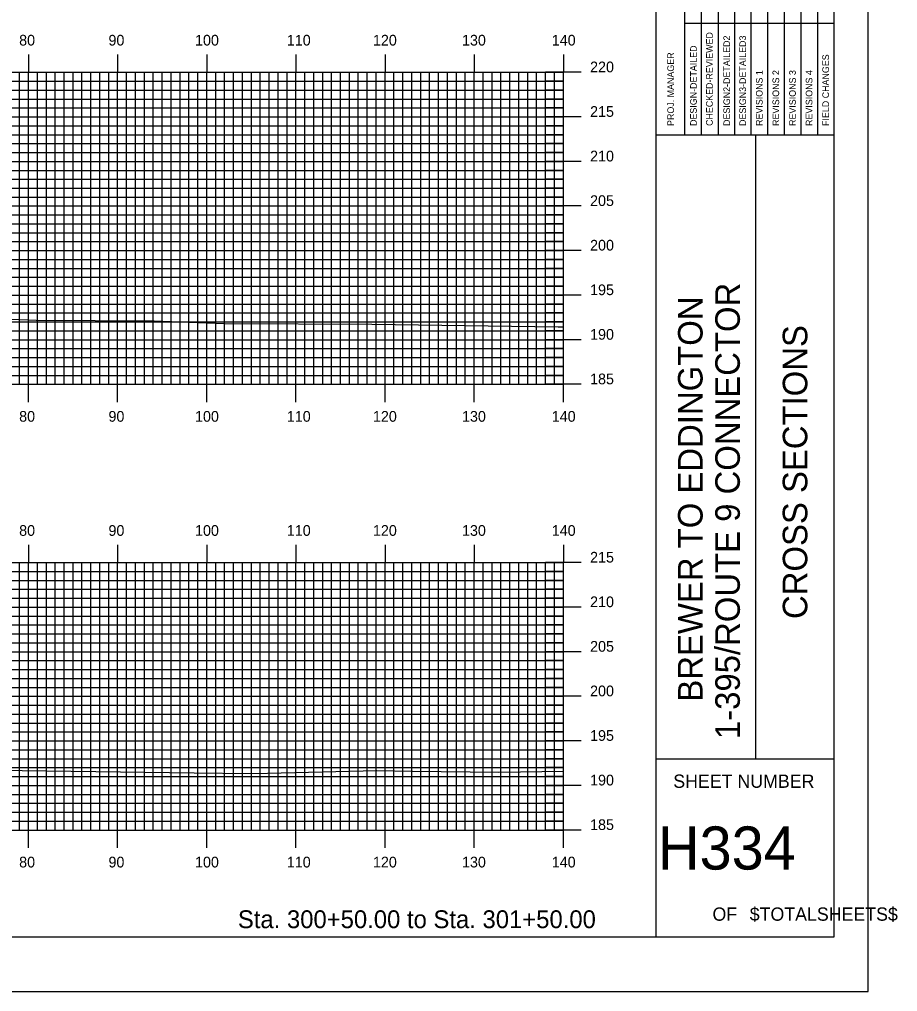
# Model space of a CAD drawing. Extents: x 1815702 to 1816046, y 442591 to 442811.
# Drawn here: x 1815947 to 1816045.5, y 442590.5 to 442699.6 of the extents above; entities that cross this region are included whole.
import ezdxf

# ---------------------------------------------------------------- set-up
doc = ezdxf.new("R2010")
doc.units = 0
for name, color, linetype in [('BORDER', 7, 'Continuous'), ('H_V ANNOTATION', 7, 'Continuous'), ('MAJOR', 7, 'Continuous'), ('MINOR', 7, 'Continuous'), ('PLOT BOUNDARY', 7, 'Continuous'), ('S_Roadway_Centerline', 7, 'Continuous')]:
    doc.layers.add(name, color=color, linetype=linetype)

msp = doc.modelspace()

# ---------------------------------------------------------------- linework, layer by layer
at = {"layer": 'BORDER'}
for p, q in [((1816018.45, 442596.67), (1816018.45, 442806.67)), ((1816018.45, 442686.67), (1816038.45, 442686.67)), ((1816029.63, 442616.67), (1816029.63, 442686.67)), ((1816018.45, 442616.67), (1816038.45, 442616.67))]:
    msp.add_line(p, q, dxfattribs=at)
msp.add_lwpolyline([(1815718.45, 442596.67), (1816038.45, 442596.67), (1816038.45, 442806.67), (1815718.45, 442806.67)], close=True, dxfattribs=at)
for points in [[(1816023.54, 442686.68), (1816023.54, 442721.67)], [(1816025.41, 442721.67), (1816025.41, 442686.68)], [(1816027.27, 442686.68), (1816027.27, 442721.67)], [(1816029.13, 442686.68), (1816029.13, 442721.67)], [(1816031, 442686.68), (1816031, 442721.67)], [(1816032.86, 442686.68), (1816032.86, 442721.67)], [(1816034.72, 442686.68), (1816034.72, 442721.67)], [(1816036.59, 442686.68), (1816036.59, 442721.67)], [(1816021.68, 442686.68), (1816021.68, 442720.26)], [(1816021.68, 442699.17), (1816038.45, 442699.17)]]:
    msp.add_lwpolyline(points, dxfattribs=at)
at = {"layer": 'MAJOR'}
for p, q in [((1815948.05, 442695.67), (1815948.05, 442693.67)), ((1815958.05, 442695.67), (1815958.05, 442693.67)), ((1815968.05, 442695.67), (1815968.05, 442693.67)), ((1815978.05, 442695.67), (1815978.05, 442693.67)), ((1815988.05, 442695.67), (1815988.05, 442693.67)), ((1815998.05, 442695.67), (1815998.05, 442693.67)), ((1816008.05, 442695.67), (1816008.05, 442693.67)), ((1815728.05, 442693.67), (1816008.05, 442693.67)), ((1815728.05, 442693.67), (1816008.05, 442693.67)), ((1815948.05, 442658.67), (1815948.05, 442693.67)), ((1815958.05, 442658.67), (1815958.05, 442693.67)), ((1815968.05, 442658.67), (1815968.05, 442693.67)), ((1815978.05, 442658.67), (1815978.05, 442693.67)), ((1815988.05, 442658.67), (1815988.05, 442693.67)), ((1815998.05, 442658.67), (1815998.05, 442693.67)), ((1816010.05, 442693.67), (1816006.04, 442693.67)), ((1816008.05, 442658.67), (1816008.05, 442693.67)), ((1816008.05, 442658.67), (1816008.05, 442693.67)), ((1815728.05, 442688.67), (1816008.05, 442688.67)), ((1816010.05, 442688.67), (1816006.04, 442688.67)), ((1815728.05, 442683.67), (1816008.05, 442683.67)), ((1816010.05, 442683.67), (1816006.04, 442683.67)), ((1815728.05, 442678.67), (1816008.05, 442678.67)), ((1816010.05, 442678.67), (1816006.04, 442678.67)), ((1815728.05, 442673.67), (1816008.05, 442673.67)), ((1816010.05, 442673.67), (1816006.04, 442673.67)), ((1815728.05, 442668.67), (1816008.05, 442668.67)), ((1816010.05, 442668.67), (1816006.04, 442668.67)), ((1815728.05, 442663.67), (1816008.05, 442663.67)), ((1816010.05, 442663.67), (1816006.04, 442663.67)), ((1815728.05, 442658.67), (1816008.05, 442658.67)), ((1815728.05, 442658.67), (1816008.05, 442658.67)), ((1815948.05, 442656.66), (1815948.05, 442658.67)), ((1815958.05, 442656.66), (1815958.05, 442658.67)), ((1815968.05, 442656.66), (1815968.05, 442658.67)), ((1815978.05, 442656.66), (1815978.05, 442658.67)), ((1815988.05, 442656.66), (1815988.05, 442658.67)), ((1815998.05, 442656.66), (1815998.05, 442658.67)), ((1816010.05, 442658.67), (1816006.04, 442658.67)), ((1816008.05, 442656.66), (1816008.05, 442658.67)), ((1815948.05, 442640.67), (1815948.05, 442638.67)), ((1815958.05, 442640.67), (1815958.05, 442638.67)), ((1815968.05, 442640.67), (1815968.05, 442638.67)), ((1815978.05, 442640.67), (1815978.05, 442638.67)), ((1815988.05, 442640.67), (1815988.05, 442638.67)), ((1815998.05, 442640.67), (1815998.05, 442638.67)), ((1816008.05, 442640.67), (1816008.05, 442638.67)), ((1815728.05, 442638.67), (1816008.05, 442638.67)), ((1815728.05, 442638.67), (1816008.05, 442638.67)), ((1815948.05, 442608.67), (1815948.05, 442638.67)), ((1815958.05, 442608.67), (1815958.05, 442638.67)), ((1815968.05, 442608.67), (1815968.05, 442638.67)), ((1815978.05, 442608.67), (1815978.05, 442638.67)), ((1815988.05, 442608.67), (1815988.05, 442638.67)), ((1815998.05, 442608.67), (1815998.05, 442638.67)), ((1816010.05, 442638.67), (1816006.04, 442638.67)), ((1816008.05, 442608.67), (1816008.05, 442638.67)), ((1816008.05, 442608.67), (1816008.05, 442638.67)), ((1815728.05, 442633.67), (1816008.05, 442633.67)), ((1816010.05, 442633.67), (1816006.04, 442633.67)), ((1815728.05, 442628.67), (1816008.05, 442628.67)), ((1816010.05, 442628.67), (1816006.04, 442628.67)), ((1815728.05, 442623.67), (1816008.05, 442623.67)), ((1816010.05, 442623.67), (1816006.04, 442623.67)), ((1815728.05, 442618.67), (1816008.05, 442618.67)), ((1816010.05, 442618.67), (1816006.04, 442618.67)), ((1815728.05, 442613.67), (1816008.05, 442613.67)), ((1816010.05, 442613.67), (1816006.04, 442613.67)), ((1815728.05, 442608.67), (1816008.05, 442608.67)), ((1815728.05, 442608.67), (1816008.05, 442608.67)), ((1815948.05, 442606.66), (1815948.05, 442608.67)), ((1815958.05, 442606.66), (1815958.05, 442608.67)), ((1815968.05, 442606.66), (1815968.05, 442608.67)), ((1815978.05, 442606.66), (1815978.05, 442608.67)), ((1815988.05, 442606.66), (1815988.05, 442608.67)), ((1815998.05, 442606.66), (1815998.05, 442608.67)), ((1816010.05, 442608.67), (1816006.04, 442608.67)), ((1816008.05, 442606.66), (1816008.05, 442608.67))]:
    msp.add_line(p, q, dxfattribs=at)
at = {"layer": 'MINOR'}
for p, q in [((1815947.05, 442658.67), (1815947.05, 442693.67)), ((1815949.05, 442658.67), (1815949.05, 442693.67)), ((1815950.05, 442658.67), (1815950.05, 442693.67)), ((1815951.05, 442658.67), (1815951.05, 442693.67)), ((1815952.05, 442658.67), (1815952.05, 442693.67)), ((1815953.05, 442658.67), (1815953.05, 442693.67)), ((1815954.05, 442658.67), (1815954.05, 442693.67)), ((1815955.05, 442658.67), (1815955.05, 442693.67)), ((1815956.05, 442658.67), (1815956.05, 442693.67)), ((1815957.05, 442658.67), (1815957.05, 442693.67)), ((1815959.05, 442658.67), (1815959.05, 442693.67)), ((1815960.05, 442658.67), (1815960.05, 442693.67)), ((1815961.05, 442658.67), (1815961.05, 442693.67)), ((1815962.05, 442658.67), (1815962.05, 442693.67)), ((1815963.05, 442658.67), (1815963.05, 442693.67)), ((1815964.05, 442658.67), (1815964.05, 442693.67)), ((1815965.05, 442658.67), (1815965.05, 442693.67)), ((1815966.05, 442658.67), (1815966.05, 442693.67)), ((1815967.05, 442658.67), (1815967.05, 442693.67)), ((1815969.05, 442658.67), (1815969.05, 442693.67)), ((1815970.05, 442658.67), (1815970.05, 442693.67)), ((1815971.05, 442658.67), (1815971.05, 442693.67)), ((1815972.05, 442658.67), (1815972.05, 442693.67)), ((1815973.05, 442658.67), (1815973.05, 442693.67)), ((1815974.05, 442658.67), (1815974.05, 442693.67)), ((1815975.05, 442658.67), (1815975.05, 442693.67)), ((1815976.05, 442658.67), (1815976.05, 442693.67)), ((1815977.05, 442658.67), (1815977.05, 442693.67)), ((1815979.05, 442658.67), (1815979.05, 442693.67)), ((1815980.05, 442658.67), (1815980.05, 442693.67)), ((1815981.05, 442658.67), (1815981.05, 442693.67)), ((1815982.05, 442658.67), (1815982.05, 442693.67)), ((1815983.05, 442658.67), (1815983.05, 442693.67)), ((1815984.05, 442658.67), (1815984.05, 442693.67)), ((1815985.05, 442658.67), (1815985.05, 442693.67)), ((1815986.05, 442658.67), (1815986.05, 442693.67)), ((1815987.05, 442658.67), (1815987.05, 442693.67)), ((1815989.05, 442658.67), (1815989.05, 442693.67)), ((1815990.05, 442658.67), (1815990.05, 442693.67)), ((1815991.05, 442658.67), (1815991.05, 442693.67)), ((1815992.05, 442658.67), (1815992.05, 442693.67)), ((1815993.05, 442658.67), (1815993.05, 442693.67)), ((1815994.05, 442658.67), (1815994.05, 442693.67)), ((1815995.05, 442658.67), (1815995.05, 442693.67)), ((1815996.05, 442658.67), (1815996.05, 442693.67)), ((1815997.05, 442658.67), (1815997.05, 442693.67)), ((1815999.05, 442658.67), (1815999.05, 442693.67)), ((1816000.05, 442658.67), (1816000.05, 442693.67)), ((1816001.05, 442658.67), (1816001.05, 442693.67)), ((1816002.05, 442658.67), (1816002.05, 442693.67)), ((1816003.05, 442658.67), (1816003.05, 442693.67)), ((1816004.05, 442658.67), (1816004.05, 442693.67)), ((1816005.05, 442658.67), (1816005.05, 442693.67)), ((1816006.05, 442658.67), (1816006.05, 442693.67)), ((1816007.05, 442658.67), (1816007.05, 442693.67)), ((1815728.05, 442692.67), (1816008.05, 442692.67)), ((1815728.05, 442691.67), (1816008.05, 442691.67)), ((1816008.05, 442692.67), (1816006.04, 442692.67)), ((1816008.05, 442691.67), (1816006.04, 442691.67)), ((1815728.05, 442690.67), (1816008.05, 442690.67)), ((1816008.05, 442690.67), (1816006.04, 442690.67)), ((1815728.05, 442689.67), (1816008.05, 442689.67)), ((1816008.05, 442689.67), (1816006.04, 442689.67)), ((1815728.05, 442687.67), (1816008.05, 442687.67)), ((1816008.05, 442687.67), (1816006.04, 442687.67)), ((1815728.05, 442686.67), (1816008.05, 442686.67)), ((1816008.05, 442686.67), (1816006.04, 442686.67)), ((1815728.05, 442685.67), (1816008.05, 442685.67)), ((1816008.05, 442685.67), (1816006.04, 442685.67)), ((1815728.05, 442684.67), (1816008.05, 442684.67)), ((1816008.05, 442684.67), (1816006.04, 442684.67)), ((1815728.05, 442682.67), (1816008.05, 442682.67)), ((1816008.05, 442682.67), (1816006.04, 442682.67)), ((1815728.05, 442681.67), (1816008.05, 442681.67)), ((1816008.05, 442681.67), (1816006.04, 442681.67)), ((1815728.05, 442680.67), (1816008.05, 442680.67)), ((1815728.05, 442679.67), (1816008.05, 442679.67)), ((1816008.05, 442680.67), (1816006.04, 442680.67)), ((1816008.05, 442679.67), (1816006.04, 442679.67)), ((1815728.05, 442677.67), (1816008.05, 442677.67)), ((1816008.05, 442677.67), (1816006.04, 442677.67)), ((1815728.05, 442676.67), (1816008.05, 442676.67)), ((1816008.05, 442676.67), (1816006.04, 442676.67)), ((1815728.05, 442675.67), (1816008.05, 442675.67)), ((1816008.05, 442675.67), (1816006.04, 442675.67)), ((1815728.05, 442674.67), (1816008.05, 442674.67)), ((1816008.05, 442674.67), (1816006.04, 442674.67)), ((1815728.05, 442672.67), (1816008.05, 442672.67)), ((1816008.05, 442672.67), (1816006.04, 442672.67)), ((1815728.05, 442671.67), (1816008.05, 442671.67)), ((1816008.05, 442671.67), (1816006.04, 442671.67)), ((1815728.05, 442670.67), (1816008.05, 442670.67)), ((1816008.05, 442670.67), (1816006.04, 442670.67)), ((1815728.05, 442669.67), (1816008.05, 442669.67)), ((1816008.05, 442669.67), (1816006.04, 442669.67)), ((1815728.05, 442667.67), (1816008.05, 442667.67)), ((1816008.05, 442667.67), (1816006.04, 442667.67)), ((1815728.05, 442666.67), (1816008.05, 442666.67)), ((1816008.05, 442666.67), (1816006.04, 442666.67)), ((1815728.05, 442665.67), (1816008.05, 442665.67)), ((1816008.05, 442665.67), (1816006.04, 442665.67)), ((1815728.05, 442664.67), (1816008.05, 442664.67)), ((1816008.05, 442664.67), (1816006.04, 442664.67)), ((1815728.05, 442662.67), (1816008.05, 442662.67)), ((1816008.05, 442662.67), (1816006.04, 442662.67)), ((1815728.05, 442661.67), (1816008.05, 442661.67)), ((1816008.05, 442661.67), (1816006.04, 442661.67)), ((1815728.05, 442660.67), (1816008.05, 442660.67)), ((1816008.05, 442660.67), (1816006.04, 442660.67)), ((1815728.05, 442659.67), (1816008.05, 442659.67)), ((1816008.05, 442659.67), (1816006.04, 442659.67)), ((1815947.05, 442608.67), (1815947.05, 442638.67)), ((1815949.05, 442608.67), (1815949.05, 442638.67)), ((1815950.05, 442608.67), (1815950.05, 442638.67)), ((1815951.05, 442608.67), (1815951.05, 442638.67)), ((1815952.05, 442608.67), (1815952.05, 442638.67)), ((1815953.05, 442608.67), (1815953.05, 442638.67)), ((1815954.05, 442608.67), (1815954.05, 442638.67)), ((1815955.05, 442608.67), (1815955.05, 442638.67)), ((1815956.05, 442608.67), (1815956.05, 442638.67)), ((1815957.05, 442608.67), (1815957.05, 442638.67)), ((1815959.05, 442608.67), (1815959.05, 442638.67)), ((1815960.05, 442608.67), (1815960.05, 442638.67)), ((1815961.05, 442608.67), (1815961.05, 442638.67)), ((1815962.05, 442608.67), (1815962.05, 442638.67)), ((1815963.05, 442608.67), (1815963.05, 442638.67)), ((1815964.05, 442608.67), (1815964.05, 442638.67)), ((1815965.05, 442608.67), (1815965.05, 442638.67)), ((1815966.05, 442608.67), (1815966.05, 442638.67)), ((1815967.05, 442608.67), (1815967.05, 442638.67)), ((1815969.05, 442608.67), (1815969.05, 442638.67)), ((1815970.05, 442608.67), (1815970.05, 442638.67)), ((1815971.05, 442608.67), (1815971.05, 442638.67)), ((1815972.05, 442608.67), (1815972.05, 442638.67)), ((1815973.05, 442608.67), (1815973.05, 442638.67)), ((1815974.05, 442608.67), (1815974.05, 442638.67)), ((1815975.05, 442608.67), (1815975.05, 442638.67)), ((1815976.05, 442608.67), (1815976.05, 442638.67)), ((1815977.05, 442608.67), (1815977.05, 442638.67)), ((1815979.05, 442608.67), (1815979.05, 442638.67)), ((1815980.05, 442608.67), (1815980.05, 442638.67)), ((1815981.05, 442608.67), (1815981.05, 442638.67)), ((1815982.05, 442608.67), (1815982.05, 442638.67)), ((1815983.05, 442608.67), (1815983.05, 442638.67)), ((1815984.05, 442608.67), (1815984.05, 442638.67)), ((1815985.05, 442608.67), (1815985.05, 442638.67)), ((1815986.05, 442608.67), (1815986.05, 442638.67)), ((1815987.05, 442608.67), (1815987.05, 442638.67)), ((1815989.05, 442608.67), (1815989.05, 442638.67)), ((1815990.05, 442608.67), (1815990.05, 442638.67)), ((1815991.05, 442608.67), (1815991.05, 442638.67)), ((1815992.05, 442608.67), (1815992.05, 442638.67)), ((1815993.05, 442608.67), (1815993.05, 442638.67)), ((1815994.05, 442608.67), (1815994.05, 442638.67)), ((1815995.05, 442608.67), (1815995.05, 442638.67)), ((1815996.05, 442608.67), (1815996.05, 442638.67)), ((1815997.05, 442608.67), (1815997.05, 442638.67)), ((1815999.05, 442608.67), (1815999.05, 442638.67)), ((1816000.05, 442608.67), (1816000.05, 442638.67)), ((1816001.05, 442608.67), (1816001.05, 442638.67)), ((1816002.05, 442608.67), (1816002.05, 442638.67)), ((1816003.05, 442608.67), (1816003.05, 442638.67)), ((1816004.05, 442608.67), (1816004.05, 442638.67)), ((1816005.05, 442608.67), (1816005.05, 442638.67)), ((1816006.05, 442608.67), (1816006.05, 442638.67)), ((1816007.05, 442608.67), (1816007.05, 442638.67)), ((1815728.05, 442637.67), (1816008.05, 442637.67)), ((1816008.05, 442637.67), (1816006.04, 442637.67)), ((1815728.05, 442636.67), (1816008.05, 442636.67)), ((1816008.05, 442636.67), (1816006.04, 442636.67)), ((1815728.05, 442635.67), (1816008.05, 442635.67)), ((1816008.05, 442635.67), (1816006.04, 442635.67)), ((1815728.05, 442634.67), (1816008.05, 442634.67)), ((1816008.05, 442634.67), (1816006.04, 442634.67)), ((1815728.05, 442632.67), (1816008.05, 442632.67)), ((1816008.05, 442632.67), (1816006.04, 442632.67)), ((1815728.05, 442631.67), (1816008.05, 442631.67)), ((1815728.05, 442630.67), (1816008.05, 442630.67)), ((1816008.05, 442631.67), (1816006.04, 442631.67)), ((1816008.05, 442630.67), (1816006.04, 442630.67)), ((1815728.05, 442629.67), (1816008.05, 442629.67)), ((1816008.05, 442629.67), (1816006.04, 442629.67)), ((1815728.05, 442627.67), (1816008.05, 442627.67)), ((1816008.05, 442627.67), (1816006.04, 442627.67)), ((1815728.05, 442626.67), (1816008.05, 442626.67)), ((1816008.05, 442626.67), (1816006.04, 442626.67)), ((1815728.05, 442625.67), (1816008.05, 442625.67)), ((1816008.05, 442625.67), (1816006.04, 442625.67)), ((1815728.05, 442624.67), (1816008.05, 442624.67)), ((1816008.05, 442624.67), (1816006.04, 442624.67)), ((1815728.05, 442622.67), (1816008.05, 442622.67)), ((1816008.05, 442622.67), (1816006.04, 442622.67)), ((1815728.05, 442621.67), (1816008.05, 442621.67)), ((1816008.05, 442621.67), (1816006.04, 442621.67)), ((1815728.05, 442620.67), (1816008.05, 442620.67)), ((1816008.05, 442620.67), (1816006.04, 442620.67)), ((1815728.05, 442619.67), (1816008.05, 442619.67)), ((1816008.05, 442619.67), (1816006.04, 442619.67)), ((1815728.05, 442617.67), (1816008.05, 442617.67)), ((1816008.05, 442617.67), (1816006.04, 442617.67)), ((1815728.05, 442616.67), (1816008.05, 442616.67)), ((1816008.05, 442616.67), (1816006.04, 442616.67)), ((1815728.05, 442615.67), (1816008.05, 442615.67)), ((1816008.05, 442615.67), (1816006.04, 442615.67)), ((1815728.05, 442614.67), (1816008.05, 442614.67)), ((1816008.05, 442614.67), (1816006.04, 442614.67)), ((1815728.05, 442612.67), (1816008.05, 442612.67)), ((1816008.05, 442612.67), (1816006.04, 442612.67)), ((1815728.05, 442611.67), (1816008.05, 442611.67)), ((1816008.05, 442611.67), (1816006.04, 442611.67)), ((1815728.05, 442610.67), (1816008.05, 442610.67)), ((1816008.05, 442610.67), (1816006.04, 442610.67)), ((1815728.05, 442609.67), (1816008.05, 442609.67)), ((1816008.05, 442609.67), (1816006.04, 442609.67))]:
    msp.add_line(p, q, dxfattribs=at)
at = {"layer": 'PLOT BOUNDARY'}
msp.add_lwpolyline([(1815702.26, 442590.55), (1816042.26, 442590.55), (1816042.26, 442810.55), (1815702.26, 442810.55)], close=True, dxfattribs=at)
at = {"layer": 'S_Roadway_Centerline'}
for points in [[(1815809.56, 442672.51), (1815823.05, 442671.65), (1815826.54, 442671.35), (1815836.32, 442670.69), (1815841.18, 442670.41), (1815842.31, 442670.37), (1815855.5, 442670.01), (1815860.83, 442669.64), (1815869.42, 442669.24), (1815877.56, 442668.97), (1815882.7, 442668.66), (1815894.49, 442667.72), (1815896.09, 442667.63), (1815900.12, 442667.6), (1815912.51, 442667.31), (1815923.93, 442666.7), (1815928.95, 442666.66), (1815937.45, 442666.3), (1815948.91, 442665.88), (1815962.14, 442665.79), (1815970.07, 442665.5), (1815986.57, 442665.4), (1816007.47, 442665.13), (1816008.05, 442665.13)], [(1815941.78, 442615.41), (1815966.62, 442615.08), (1815973.04, 442615.01), (1815974.86, 442615.05), (1815987.14, 442615.33), (1815991.13, 442615.28), (1816000.83, 442615.17), (1816008.05, 442615.28)]]:
    msp.add_lwpolyline(points, dxfattribs=at)

# ---------------------------------------------------------------- texts
at = {"layer": 'BORDER'}
for s, height, p in [('CHECKED-REVIEWED', 0.7455, (1816024.81, 442687.65)), ('DESIGN2-DETAILED2', 0.7455, (1816026.75, 442687.65)), ('DESIGN3-DETAILED3', 0.7455, (1816028.54, 442687.65)), ('DESIGN-DETAILED', 0.7455, (1816023.02, 442687.65)), ('PROJ. MANAGER', 0.7455, (1816020.46, 442687.65)), ('FIELD CHANGES', 0.7455, (1816037.85, 442687.65)), ('REVISIONS 1', 0.7455, (1816030.4, 442687.65)), ('REVISIONS 2', 0.7455, (1816032.26, 442687.65)), ('REVISIONS 3', 0.7455, (1816034.13, 442687.65)), ('REVISIONS 4', 0.7455, (1816035.99, 442687.65)), ('1-395/ROUTE 9 CONNECTOR', 2.7557, (1816027.85, 442618.87)), ('BREWER TO EDDINGTON', 2.7557, (1816023.67, 442623.07)), ('CROSS SECTIONS', 2.7557, (1816035.42, 442632.34))]:
    msp.add_text(s, height=height, rotation=90, dxfattribs=at).set_placement(p)
for s, height, p in [('SHEET NUMBER', 1.4905, (1816020.38, 442613.4)), ('H334', 4.839, (1816018.66, 442604.23)), ('$TOTALSHEETS$', 1.4905, (1816028.96, 442598.49)), ('OF', 1.491, (1816024.78, 442598.49))]:
    msp.add_text(s, height=height, dxfattribs=at).set_placement(p)
at = {"layer": 'H_V ANNOTATION'}
for s, height, p in [('80', 1.2, (1815947, 442696.67)), ('90', 1.2, (1815957.02, 442696.67)), ('100', 1.2, (1815966.73, 442696.67)), ('110', 1.2, (1815977.03, 442696.67)), ('120', 1.2, (1815986.69, 442696.67)), ('130', 1.2, (1815996.68, 442696.67)), ('140', 1.2, (1816006.75, 442696.67)), ('220', 1.2, (1816011.05, 442693.67)), ('215', 1.2, (1816011.05, 442688.67)), ('210', 1.2, (1816011.05, 442683.67)), ('205', 1.2, (1816011.05, 442678.67)), ('200', 1.2, (1816011.05, 442673.67)), ('195', 1.2, (1816011.05, 442668.67)), ('190', 1.2, (1816011.05, 442663.67)), ('185', 1.2, (1816011.05, 442658.67)), ('80', 1.2, (1815947, 442654.47)), ('90', 1.2, (1815957.02, 442654.47)), ('100', 1.2, (1815966.73, 442654.47)), ('110', 1.2, (1815977.03, 442654.47)), ('120', 1.2, (1815986.69, 442654.47)), ('130', 1.2, (1815996.68, 442654.47)), ('140', 1.2, (1816006.75, 442654.47)), ('80', 1.2, (1815947, 442641.67)), ('90', 1.2, (1815957.02, 442641.67)), ('100', 1.2, (1815966.73, 442641.67)), ('110', 1.2, (1815977.03, 442641.67)), ('120', 1.2, (1815986.69, 442641.67)), ('130', 1.2, (1815996.68, 442641.67)), ('140', 1.2, (1816006.75, 442641.67)), ('215', 1.2, (1816011.05, 442638.67)), ('210', 1.2, (1816011.05, 442633.67)), ('205', 1.2, (1816011.05, 442628.67)), ('200', 1.2, (1816011.05, 442623.67)), ('195', 1.2, (1816011.05, 442618.67)), ('190', 1.2, (1816011.05, 442613.67)), ('185', 1.2, (1816011.05, 442608.67)), ('80', 1.2, (1815947, 442604.47)), ('90', 1.2, (1815957.02, 442604.47)), ('100', 1.2, (1815966.73, 442604.47)), ('110', 1.2, (1815977.03, 442604.47)), ('120', 1.2, (1815986.69, 442604.47)), ('130', 1.2, (1815996.68, 442604.47)), ('140', 1.2, (1816006.75, 442604.47)), ('Sta. 300+50.00 to Sta. 301+50.00', 2.0004, (1815971.54, 442597.66))]:
    msp.add_text(s, height=height, dxfattribs=at).set_placement(p)

doc.saveas('drawing.dxf')
